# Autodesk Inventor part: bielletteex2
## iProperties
Created: 2006-05
Part Number: bielletteex2
Document SubType Name: Modeling
Designer: Administrateur
Manufacturer: Standard
Standards Organization: Custom
Author: Administrateur
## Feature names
1. Extrusion1
2. Extrusion2
